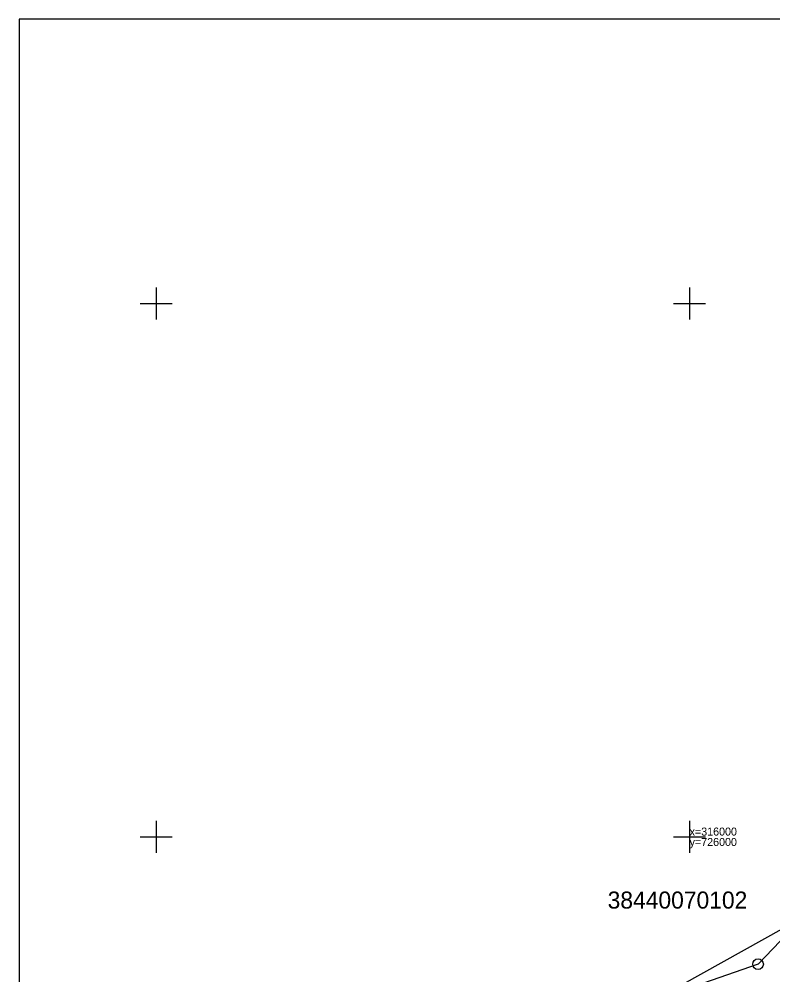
# Model space of a CAD drawing. Extents: x 316000 to 728450, y 314368 to 726000.
# Drawn here: x 725372 to 726078, y 315871 to 316766 of the extents above; entities that cross this region are included whole.
import ezdxf

# ---------------------------------------------------------------- set-up
doc = ezdxf.new("R2010")
doc.units = 0
for name, color, linetype in [('10', 7, 'Continuous'), ('24', 7, 'Continuous'), ('59', 7, 'Continuous'), ('GEOD_ELEM_####_####_#', 7, 'Continuous'), ('GEOD_KORD_####_TKST_#', 7, 'Continuous'), ('RAMI_PLAN_####_TKST_#', 7, 'Continuous'), ('RAMI_UZMR_####_####_#', 7, 'Continuous')]:
    doc.layers.add(name, color=color, linetype=linetype)

msp = doc.modelspace()

# ---------------------------------------------------------------- linework, layer by layer
at = {"layer": '10'}
msp.add_circle((726064.11, 315880.58), 5, dxfattribs=at)
at = {"layer": '24'}
for p, q in [((726130.58, 315950.18), (726064.11, 315880.58)), ((726064.11, 315880.58), (725858.2, 315809.4))]:
    msp.add_line(p, q, dxfattribs=at)
at = {"layer": 'GEOD_ELEM_####_####_#'}
for p, q in [((725500, 316515), (725500, 316500)), ((726000, 316515), (726000, 316500)), ((725485, 316500), (725500, 316500)), ((725500, 316500), (725500, 316485)), ((725500, 316500), (725515, 316500)), ((725985, 316500), (726000, 316500)), ((726000, 316500), (726000, 316485)), ((726000, 316500), (726015, 316500)), ((725500, 316015), (725500, 316000)), ((726000, 316015), (726000, 316000)), ((725485, 316000), (725500, 316000)), ((725500, 316000), (725500, 315985)), ((725500, 316000), (725515, 316000)), ((725985, 316000), (726000, 316000)), ((726000, 316000), (726000, 315985)), ((726000, 316000), (726015, 316000))]:
    msp.add_line(p, q, dxfattribs=at)
at = {"layer": 'RAMI_PLAN_####_TKST_#'}
msp.add_lwpolyline([(725371.66, 314368.28), (727955.92, 314368.28), (727955.92, 316766.42), (725371.66, 316766.42)], close=True, dxfattribs=at)
at = {"layer": 'RAMI_UZMR_####_####_#'}
msp.add_lwpolyline([(725662, 315676.73), (726089.69, 315915.19), (726207.18, 316075.15), (726354.66, 316148.59), (726468.38, 316318.09), (726620.03, 316392.72), (726621.75, 316399.51), (726696.34, 316417.27), (726741.03, 316429.64), (726920.82, 316413.39), (727228.71, 316639.18)], dxfattribs=at)

# ---------------------------------------------------------------- texts
at = {"layer": '59'}
msp.add_text('38440070102', height=16, dxfattribs=at).set_placement((725923.17, 315932.68))
at = {"layer": 'GEOD_KORD_####_TKST_#'}
for s, p in [('x=316000', (726000, 316001.12)), ('y=726000', (726000, 315991.37))]:
    msp.add_text(s, height=7.5, dxfattribs=at).set_placement(p)

doc.saveas('drawing.dxf')
